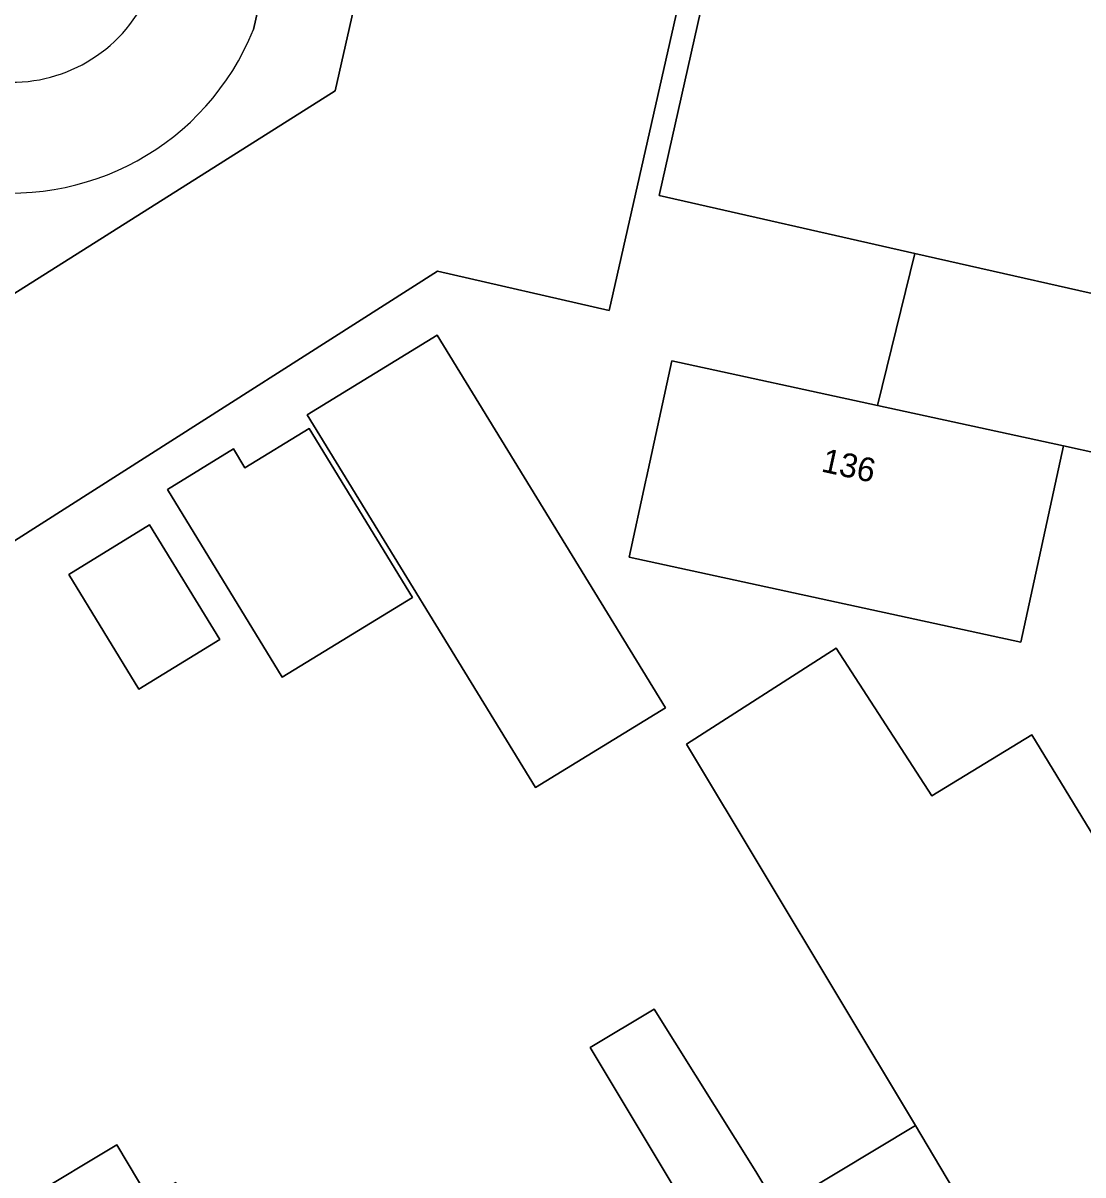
# Model space of a CAD drawing. Extents: x 161771 to 163125, y 382475 to 383179.
# Drawn here: x 162363.7 to 162408.05, y 382769.06 to 382817.29 of the extents above; entities that cross this region are included whole.
import ezdxf

# ---------------------------------------------------------------- set-up
doc = ezdxf.new("R2010")
doc.units = 0
for name, color, linetype in [('IMGEO_Erf', 7, 'Continuous'), ('IMGEO_Hek', 7, 'Continuous'), ('IMGEO_Pand', 7, 'Continuous'), ('IMGEO_Pand_nummerreeks', 7, 'Continuous'), ('IMGEO_Rijbaan_lokaal_open', 7, 'Continuous'), ('IMGEO_Verkeerseiland_open', 7, 'Continuous')]:
    doc.layers.add(name, color=color, linetype=linetype)

msp = doc.modelspace()

# ---------------------------------------------------------------- linework, layer by layer
at = {"layer": 'IMGEO_Erf'}
for points in [[(162362.501, 382805.442), (162376.753, 382814.45), (162381.514, 382835.487), (162383.737, 382845.427), (162380.23, 382846.218), (162381.561, 382852.116), (162398.029, 382848.406), (162397.956, 382848.084), (162397.916, 382848.093), (162394.404, 382832.576), (162388.22, 382805.257), (162381.031, 382806.892), (162352.312, 382788.585)], [(162419.621, 382768.808), (162417.047, 382773.095), (162414.075, 382778.046), (162416.772, 382779.665), (162414.082, 382784.148), (162414.552, 382784.43), (162416.256, 382785.452), (162414.444, 382788.736), (162415.073, 382791.621), (162414.641, 382791.715), (162408.974, 382792.949), (162410.274, 382798.919), (162407.235, 382799.581), (162405.446, 382791.362), (162389.06, 382794.93), (162389.745, 382798.078), (162389.762, 382798.155), (162389.786, 382798.264), (162390.849, 382803.149), (162399.448, 382801.277), (162401.005, 382807.642), (162390.309, 382810.062), (162398.872, 382848.19)], [(162377.687, 382836.351), (162373.333, 382817.01)], [(162396.095, 382768.159), (162401.036, 382771.125), (162391.452, 382787.091), (162397.721, 382791.12), (162401.729, 382784.934), (162405.913, 382787.488), (162413.579, 382774.899), (162415.322, 382771.996), (162417.896, 382767.709)], [(162394.294, 382762.96), (162387.432, 382774.391), (162390.105, 382775.995), (162394.357, 382769.211), (162397.103, 382764.646)], [(162363.947, 382768.12), (162367.62, 382770.316), (162368.958, 382768.076)]]:
    msp.add_lwpolyline(points, dxfattribs=at)
for points in [[(162381.026, 382804.221), (162390.58, 382788.612), (162385.134, 382785.278), (162375.58, 382800.888)], [(162372.5, 382799.454), (162372.981, 382798.668), (162375.669, 382800.313), (162379.997, 382793.242), (162374.544, 382789.905), (162369.736, 382797.761)], [(162368.99, 382796.273), (162371.928, 382791.472), (162368.544, 382789.401), (162365.606, 382794.201)]]:
    msp.add_lwpolyline(points, close=True, dxfattribs=at)
msp.add_arc((162363.211, 382821.081), 10.91, 259.5433, 338.0921, dxfattribs=at)
at = {"layer": 'IMGEO_Hek'}
msp.add_lwpolyline([(162401.005, 382807.642), (162399.448, 382801.277)], dxfattribs=at)
at = {"layer": 'IMGEO_Pand'}
msp.add_lwpolyline([(162352.312, 382788.585), (162381.031, 382806.892), (162388.22, 382805.257), (162394.404, 382832.576), (162397.916, 382848.093), (162397.956, 382848.084), (162398.029, 382848.406), (162381.561, 382852.116), (162380.23, 382846.218), (162383.737, 382845.427), (162381.514, 382835.487), (162376.753, 382814.45), (162362.501, 382805.442)], dxfattribs=at)
for points in [[(162398.872, 382848.19), (162390.309, 382810.062), (162401.005, 382807.642), (162411.148, 382805.346), (162414.898, 382821.927), (162419.769, 382843.463), (162414.562, 382844.641), (162398.956, 382848.171)], [(162375.58, 382800.888), (162385.134, 382785.278), (162390.58, 382788.612), (162381.026, 382804.221)], [(162389.745, 382798.078), (162389.06, 382794.93), (162405.446, 382791.362), (162407.235, 382799.581), (162399.448, 382801.277), (162390.849, 382803.149), (162389.786, 382798.264), (162389.762, 382798.155)], [(162372.981, 382798.668), (162372.5, 382799.454), (162369.736, 382797.761), (162374.544, 382789.905), (162379.997, 382793.242), (162375.669, 382800.313)], [(162365.606, 382794.201), (162368.544, 382789.401), (162371.928, 382791.472), (162368.99, 382796.273)], [(162405.913, 382787.488), (162401.729, 382784.934), (162397.721, 382791.12), (162391.452, 382787.091), (162401.036, 382771.125), (162402.329, 382768.971), (162407.01, 382761.174), (162417.896, 382767.709), (162415.322, 382771.996), (162413.579, 382774.899)], [(162391.866, 382761.502), (162393.424, 382758.907), (162395.997, 382754.62), (162401.234, 382757.764), (162398.661, 382762.051), (162397.103, 382764.646), (162394.357, 382769.211), (162390.105, 382775.995), (162387.432, 382774.391), (162394.294, 382762.96)], [(162402.329, 382768.971), (162401.036, 382771.125), (162396.095, 382768.159), (162397.388, 382766.005), (162399.495, 382762.495), (162402.069, 382758.208), (162407.01, 382761.174)], [(162379.476, 382750.464), (162377.899, 382753.104), (162372.424, 382762.273), (162374.511, 382763.519), (162372.674, 382766.596), (162372.02, 382766.205), (162371.206, 382767.568), (162370.898, 382767.385), (162370.083, 382768.749), (162368.958, 382768.076), (162367.62, 382770.316), (162363.947, 382768.12), (162368.436, 382760.612), (162370.095, 382760.289), (162373.591, 382754.442), (162371.894, 382753.428), (162371.308, 382750), (162371.152, 382749.085), (162372.738, 382746.434), (162375.305, 382742.143), (162382.041, 382746.172), (162379.753, 382750)]]:
    msp.add_lwpolyline(points, close=True, dxfattribs=at)
at = {"layer": 'IMGEO_Rijbaan_lokaal_open'}
for points in [[(162373.333, 382817.01), (162377.687, 382836.351), (162381.526, 382853.218), (162376.895, 382854.242), (162376.639, 382853.05), (162376.499, 382852.425), (162368.812, 382818.258)], [(162446.392, 382787.06), (162448.264, 382795.747), (162448.511, 382796.872), (162434.638, 382800.011), (162428.836, 382801.323), (162417.285, 382803.957), (162411.148, 382805.346), (162401.005, 382807.642), (162399.448, 382801.277), (162407.235, 382799.581), (162410.274, 382798.919), (162415.942, 382797.685), (162418.96, 382797.027), (162421.977, 382796.37), (162424.992, 382795.714), (162436.645, 382793.176), (162438.881, 382789.461), (162439.945, 382789.15)]]:
    msp.add_lwpolyline(points, dxfattribs=at)
for centre, radius, start, end in [((162363.226, 382821.054), 6.247, 262.7717, 333.4097), ((162363.211, 382821.081), 10.91, 259.5433, 338.0921)]:
    msp.add_arc(centre, radius, start, end, dxfattribs=at)
at = {"layer": 'IMGEO_Verkeerseiland_open'}
msp.add_arc((162363.226, 382821.054), 6.247, 262.7717, 333.4097, dxfattribs=at)

# ---------------------------------------------------------------- texts
at = {"layer": 'IMGEO_Pand_nummerreeks'}
msp.add_text('136', height=1, rotation=347.5844, dxfattribs=at).set_placement((162397.056, 382798.518))

doc.saveas('drawing.dxf')
